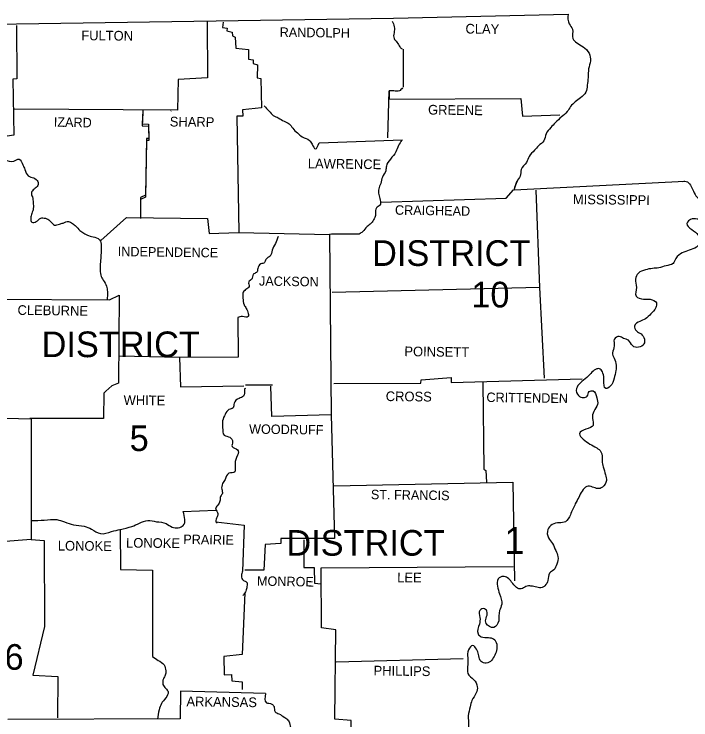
# Model space of a CAD drawing. Extents: x -17742 to 32032, y -17264 to 5867.
# Drawn here: x -16002 to -14349, y -8859 to -7133 of the extents above; entities that cross this region are included whole.
import ezdxf

# ---------------------------------------------------------------- set-up
doc = ezdxf.new("R2010")
doc.units = 0
for name, color, linetype in [('1', 7, 'Continuous'), ('2', 7, 'Continuous'), ('3', 7, 'Continuous')]:
    doc.layers.add(name, color=color, linetype=linetype)

msp = doc.modelspace()

# ---------------------------------------------------------------- linework, layer by layer
at = {"layer": '1'}
for p, q in [((-14779, -7556.5), (-14772.4, -7540.5)), ((-14780.6, -7563.1), (-14774, -7542.7)), ((-15436.7, -8039.7), (-15371.2, -8039.7))]:
    msp.add_line(p, q, dxfattribs=at)
for points in [[(-17667.8, -7158.5), (-16777.9, -7159.1), (-15996.9, -7157.4), (-15075.6, -7143.1), (-14648.6, -7133.2)], [(-15996.9, -7160.7), (-15995.8, -7291.7), (-16005.2, -7292.3), (-16003.5, -7429.3), (-16042.1, -7434.8), (-16038.8, -7471.7), (-16025.5, -7488.8), (-16026.6, -7532.2), (-16101.5, -7535), (-16104.2, -7602.1), (-16172.5, -7604.3), (-16175.8, -7685.8), (-16171.9, -7692.4), (-16170.3, -7822.3), (-16052.5, -7830), (-16054.2, -8120), (-15960.6, -8122.8), (-15960.6, -8417.8), (-16034.4, -8423.3), (-16039.9, -8488.2), (-16163.7, -8488.8)], [(-15530.8, -7152.5), (-15529.7, -7289), (-15601.2, -7292.8), (-15603.4, -7367.7), (-16001.3, -7365.5)], [(-15491.2, -7153), (-15492.8, -7166.3), (-15481.8, -7167.9), (-15482.3, -7174.5), (-15469.7, -7177.3), (-15468.6, -7186.1), (-15462.5, -7189.9), (-15460.9, -7216.3), (-15429.5, -7219.6), (-15429.5, -7243.3), (-15418, -7245), (-15418, -7254.3), (-15408, -7257.1), (-15408.6, -7289), (-15399.8, -7290.6), (-15397.6, -7362.7), (-15444.4, -7367.1), (-15443.8, -7382.5), (-15458.1, -7383.1), (-15453.2, -7667.1), (-15231.4, -7672), (-15227.5, -8113.4), (-15372.3, -8117.3), (-15375, -8043)], [(-15051.4, -7219.1), (-15051.4, -7312.1)], [(-15088.8, -7435.9), (-15086.1, -7320.9), (-15086.1, -7341.3), (-14764.1, -7339.6), (-14759.7, -7382.5), (-14668.9, -7379.2)], [(-15688.2, -7369.3), (-15689.3, -7401.3), (-15673.9, -7402.4), (-15673.3, -7437.6), (-15678.8, -7437.6), (-15681, -7576.3), (-15693.7, -7581.8), (-15693.7, -7628)], [(-15688.2, -7374.3), (-15689.3, -7406.2), (-15673.9, -7407.3), (-15673.3, -7442.5), (-15678.8, -7442.5), (-15681, -7581.2), (-15693.7, -7586.7), (-15693.7, -7633)], [(-15619.4, -7370.4), (-15618.8, -7369.9)], [(-15257.3, -7448), (-15053.1, -7440.9)], [(-14780.6, -7563.1), (-14362.9, -7541.6)], [(-15105.4, -7593.3), (-14799.9, -7583.4), (-14781.7, -7562.5)], [(-14727.8, -7563.6), (-14718.5, -7801.9), (-14707.4, -8023.7)], [(-15790.5, -7686.9), (-15727.8, -7630.2), (-15529.7, -7633), (-15525.8, -7669.8), (-15453.7, -7667.1)], [(-15159.3, -7670.9), (-15226.4, -7670.9), (-15231.4, -7672)], [(-14718.5, -7801.9), (-15225.3, -7813.5)], [(-16052.5, -7830), (-15769.6, -7831.6), (-15745.4, -7820.1), (-15747.1, -8035.3), (-15763.6, -8042.4), (-15778.4, -8055.1), (-15783.4, -8060), (-15783.9, -8121.7), (-15963.9, -8121.7)], [(-15455.9, -7875.1), (-15454.8, -7972), (-15597.9, -7972.5), (-15744.9, -7969.8)], [(-15597.9, -7972.5), (-15595.7, -8044.6), (-15441.1, -8041.9)], [(-15220.9, -8036.4), (-15008.5, -8035.3), (-15007.9, -8027.6), (-14934.2, -8022.1), (-14934.2, -8033.6), (-14613.9, -8024.8)], [(-14857.1, -8033.6), (-14854.4, -8245.5), (-14849.4, -8248.8), (-14847.8, -8277.4)], [(-15436.7, -8049), (-15439.4, -8049.6)], [(-15227.5, -8113.4), (-15219.3, -8415), (-15350.3, -8415.6), (-15350.8, -8427.7), (-15388.8, -8429.9), (-15392.1, -8492.6), (-15438.3, -8492.6)], [(-15220.9, -8286.8), (-14783.9, -8278)], [(-14783.9, -8278), (-14779.5, -8519)], [(-15589.1, -8349.5), (-15509.3, -8345.7)], [(-15509.3, -8374.3), (-15440.5, -8383.1), (-15444.4, -8495.4)], [(-15743.2, -8392.4), (-15742.1, -8491), (-15664.5, -8492.6), (-15664, -8703.9)], [(-15960.6, -8417.8), (-15928.7, -8420), (-15928.1, -8630.2), (-15956.8, -8749.6), (-15895.7, -8752.4), (-15896.2, -8853.6)], [(-15294.1, -8418.3), (-15294.7, -8486.6), (-15269.4, -8486.6), (-15268.3, -8524.5), (-15252.3, -8526.2)], [(-15220.9, -8974.7), (-15178, -8972), (-15178.6, -8860.2), (-15218.7, -8857.5), (-15216.5, -8639), (-15251.2, -8634), (-15252.3, -8487.1), (-14782.8, -8483.8)], [(-15438.3, -8548.2), (-15444.9, -8699), (-15490.1, -8703.9), (-15489, -8748.5), (-15470.8, -8748), (-15470.2, -8763.4), (-15445.5, -8766.1), (-15444.9, -8784.3)], [(-15215.4, -8716.6), (-14905, -8708.9)], [(-15387.7, -8794.2), (-15595.7, -8788.7), (-15596.8, -8856.4), (-16017.8, -8858)]]:
    msp.add_lwpolyline(points, dxfattribs=at)
for points in [[(-14648.6, -7133.2), (-14645.8, -7157.4), (-14638.1, -7170.1), (-14637, -7193.2), (-14627.6, -7203.1), (-14611.7, -7213), (-14597.4, -7229), (-14594.1, -7247.7), (-14598.5, -7267), (-14599.6, -7288.4), (-14601.8, -7307.1), (-14605.1, -7324.2), (-14618.3, -7338), (-14630.9, -7347.9), (-14642.5, -7359.4), (-14650.8, -7371.5), (-14665.1, -7384.7), (-14679.4, -7398.5), (-14690.9, -7410.6), (-14702.5, -7426), (-14708, -7443.1), (-14720.7, -7455.2), (-14730.6, -7466.2), (-14743.8, -7481.1), (-14750.4, -7495.9), (-14763, -7513), (-14765.8, -7529.5), (-14774, -7542.7), (-14774.6, -7544.9)], [(-15078.4, -7150.3), (-15073.4, -7164.1), (-15074, -7178.9), (-15074, -7192.7), (-15066.8, -7202), (-15059.7, -7213.6), (-15054.2, -7218.5)], [(-15053.6, -7313.7), (-15060.8, -7320.9), (-15074.5, -7320.9), (-15086.1, -7320.9)], [(-15391.5, -7357.8), (-15379.4, -7370.4), (-15369, -7380.9), (-15356.9, -7386.9), (-15342.6, -7395.2), (-15329.9, -7401.8), (-15321.6, -7412.3), (-15310.1, -7423.8), (-15298.5, -7433.2), (-15280.4, -7442), (-15274.3, -7451.3), (-15266.1, -7462.9), (-15257.3, -7448)], [(-15054.7, -7441.4), (-15063, -7454.6), (-15069.6, -7470), (-15082.8, -7487.7), (-15092.7, -7504.7), (-15094.3, -7516.3), (-15102.1, -7531.7), (-15106.5, -7547.1), (-15111.4, -7560.3), (-15111.4, -7574.1), (-15107.6, -7587.8), (-15108.7, -7600.5), (-15116.9, -7606.5), (-15119.1, -7622.5), (-15122.4, -7633.5), (-15129.6, -7644.5), (-15140, -7652.8), (-15151, -7665.4), (-15159.3, -7670.9)], [(-16025.5, -7488.8), (-16003.5, -7492.6), (-15990.3, -7487.7), (-15981, -7502), (-15976, -7513), (-15967.8, -7528.9), (-15954.6, -7533.9), (-15944.6, -7542.7), (-15944.6, -7552.1), (-15953.4, -7560.9), (-15960.1, -7569.7), (-15957.9, -7580.1), (-15955.7, -7594.4), (-15955.7, -7608.2), (-15959, -7620.8), (-15961.7, -7632.4), (-15959, -7642.3), (-15948.5, -7640.7), (-15937.5, -7632.4), (-15925.9, -7632.4), (-15914.9, -7638.5), (-15903.4, -7648.9), (-15891.8, -7646.7), (-15882.5, -7644), (-15869.2, -7640.1), (-15859.9, -7645.1), (-15851.6, -7651.7), (-15841.7, -7662.1), (-15832.4, -7668.7), (-15820.3, -7674.8), (-15805.4, -7678.6), (-15791.6, -7688), (-15789.4, -7703.9), (-15790, -7717.7), (-15791.1, -7734.8), (-15792.2, -7753.5), (-15790.5, -7771.6), (-15784.5, -7783.8), (-15776.8, -7798.1), (-15774.6, -7811.3), (-15775.1, -7832.2)], [(-14369, -7542.1), (-14362.9, -7541.6), (-14344.2, -7561.4), (-14336, -7577.9), (-14323.9, -7587.3), (-14310.1, -7592.2), (-14299.6, -7604.9), (-14292.5, -7618.6), (-14296.3, -7630.8), (-14311.7, -7631.9), (-14328.8, -7634.6), (-14345.3, -7634.1), (-14358.5, -7645.1), (-14346.4, -7659.9), (-14330.5, -7673.7), (-14326.1, -7688.5), (-14334.9, -7702.8), (-14352.5, -7710.6), (-14369.5, -7717.2), (-14384.9, -7730.4), (-14392.1, -7743), (-14409.2, -7748.5), (-14426.8, -7753.5), (-14442.2, -7755.1), (-14459.8, -7758.4), (-14476.9, -7766.7), (-14484, -7781), (-14481.8, -7801.4), (-14482.4, -7822.8), (-14464.2, -7830), (-14448.2, -7830.5), (-14432.8, -7838.8), (-14434.5, -7850.9), (-14446, -7866.3), (-14459.8, -7878.4), (-14473.5, -7884.5), (-14486.2, -7896), (-14481.8, -7907.6), (-14470.2, -7915.3), (-14462, -7927.9), (-14463.1, -7939.5), (-14476.3, -7947.8), (-14490.6, -7944.5), (-14501.1, -7930.7), (-14513.2, -7926.3), (-14523.6, -7921.3), (-14535.7, -7928.5), (-14535.7, -7944.5), (-14540.1, -7961.5), (-14536.3, -7974.2), (-14531.3, -7991.8), (-14531.9, -8005), (-14536.3, -8023.7), (-14545.6, -8043), (-14556.7, -8049), (-14561.1, -8028.1), (-14563.3, -8011), (-14569.9, -8001.1), (-14578.7, -8000.6), (-14590.2, -8008.8), (-14602.9, -8021.5), (-14618.8, -8035.3), (-14628.2, -8049), (-14623.2, -8066.1), (-14611.1, -8070.5), (-14601.8, -8067.2), (-14596.8, -8056.2), (-14587.5, -8054.5), (-14578.7, -8071.6)], [(-15357.4, -7677), (-15364, -7694), (-15371.7, -7710.6), (-15376.7, -7724.9), (-15387.1, -7733.1), (-15390.4, -7740.8), (-15399.8, -7744.1), (-15406.9, -7755.1), (-15410.3, -7765), (-15418, -7769.4), (-15421.8, -7781.5), (-15429, -7788.2), (-15428.4, -7799.2), (-15436.7, -7806.9), (-15443.3, -7815.7), (-15443.3, -7827.8), (-15440.5, -7843.7), (-15435, -7853.1), (-15430.1, -7865.2), (-15430.6, -7872.9), (-15444.4, -7872.9), (-15455.9, -7875.1)], [(-15439.4, -8049.6), (-15442.2, -8067.7), (-15452.6, -8072.7), (-15464.7, -8084.8), (-15467.5, -8095.8), (-15477.4, -8100.2), (-15486.7, -8111.8), (-15492.8, -8127.7), (-15492.8, -8144.2), (-15489, -8162.9), (-15475.2, -8167.9), (-15468.6, -8178.9), (-15469.7, -8190.5), (-15456.5, -8198.2), (-15454.3, -8204.8), (-15456.5, -8211.9), (-15462.5, -8232.3), (-15462, -8246), (-15463.1, -8252.1), (-15477.9, -8256), (-15486.7, -8270.8), (-15492.8, -8281.3), (-15495, -8295), (-15493.4, -8304.9), (-15497.8, -8312.6), (-15499.4, -8324.2), (-15504.9, -8334.1), (-15509.9, -8343.5), (-15504.4, -8354.5), (-15506, -8362.2), (-15509.3, -8374.3), (-15506.6, -8378.1)], [(-14578.7, -8071.6), (-14576.5, -8087.5), (-14585.8, -8104.6), (-14589.1, -8121.7), (-14587.5, -8138.7), (-14605.1, -8148.1), (-14620.5, -8159.1), (-14611.7, -8172.3), (-14595.2, -8184.4), (-14578.7, -8193.8), (-14568.2, -8203.1), (-14565.5, -8225.7), (-14562.7, -8240), (-14557.2, -8259.8), (-14555, -8273.6), (-14564.9, -8290.1), (-14576.5, -8293.4), (-14588.6, -8289.5), (-14602.9, -8288.4), (-14614.4, -8299.4), (-14622.7, -8314.8), (-14630.9, -8330.3), (-14637, -8343.5), (-14643.1, -8357.8), (-14655.2, -8374.3), (-14670, -8377), (-14687.6, -8381.4), (-14698.1, -8393.5), (-14696.4, -8413.9), (-14686.5, -8427.7), (-14678.8, -8444.7), (-14673.3, -8459.6), (-14676.1, -8478.3), (-14683.8, -8492.1), (-14693.7, -8500.3), (-14698.1, -8517.9), (-14705.2, -8531.1), (-14711.9, -8535.5), (-14725.1, -8534.4), (-14739.4, -8531.7), (-14751.5, -8532.8), (-14763, -8538.8), (-14774.6, -8535), (-14786.7, -8521.8), (-14796.6, -8511.9), (-14807.6, -8508), (-14819.2, -8514.1), (-14821.4, -8532.2), (-14815.9, -8550.9), (-14810.9, -8576.3), (-14815.9, -8591.7), (-14817.5, -8617)], [(-15959.5, -8371.5), (-15928.7, -8370.4), (-15898.4, -8369.3), (-15879.2, -8374.8), (-15857.1, -8382), (-15831.3, -8385.3), (-15813.1, -8392.4), (-15791.6, -8403.4), (-15764.1, -8398.5), (-15742.7, -8393), (-15714.6, -8385.8), (-15696.4, -8378.1), (-15675.5, -8371.5), (-15654.6, -8374.3), (-15630.9, -8378.7), (-15616.1, -8387.5), (-15589.1, -8383.6), (-15589.1, -8349.5)], [(-15444.4, -8495.4), (-15446.6, -8506.4), (-15442.2, -8517.9), (-15434.5, -8521.8), (-15433.4, -8532.8), (-15436.1, -8543.8), (-15438.3, -8548.2), (-15443.3, -8554.8)], [(-14817.5, -8617), (-14830.2, -8632.9), (-14848.9, -8623), (-14848.9, -8609.8), (-14846.1, -8596.1), (-14852.7, -8587.3), (-14864.3, -8591.1), (-14864.3, -8608.2), (-14865.4, -8624.7), (-14868.7, -8648.4), (-14861, -8655.5), (-14843.4, -8657.7), (-14830.7, -8661), (-14823, -8673.7), (-14823.6, -8689.1), (-14829.6, -8703.9), (-14838.4, -8716), (-14852.2, -8720.5), (-14863.2, -8713.3), (-14867.6, -8699), (-14872.6, -8686.3), (-14881.9, -8677), (-14891.8, -8687.4), (-14894, -8706.7), (-14893.5, -8723.2), (-14893.5, -8745.8), (-14879.2, -8760.6), (-14870.4, -8777.7), (-14873.1, -8793.1), (-14883.6, -8811.3), (-14888, -8827.2), (-14892.4, -8848.7), (-14891.8, -8872.3), (-14895.7, -8895.5), (-14903.4, -8910.9), (-14917.7, -8923.5), (-14927, -8931.8), (-14934.7, -8940), (-14938.6, -8956.6), (-14941.3, -8968.1), (-14951.8, -8981.9), (-14960.1, -8983), (-14966.7, -8977.5), (-14968.9, -8968.1), (-14968.9, -8958.8), (-14973.3, -8949.4), (-14987, -8945.5), (-14998, -8946.1), (-15003, -8953.8), (-14995.8, -8975.3), (-14993.1, -8989), (-14996.9, -9007.7), (-14994.7, -9009.9), (-15014.5, -9020.4), (-15030.5, -9022), (-15043.7, -9025.9), (-15056.4, -9034.2), (-15062.4, -9046.3), (-15071.2, -9056.2), (-15078.9, -9065.5), (-15089.4, -9069.9), (-15101, -9067.7), (-15116.4, -9066.1), (-15125.2, -9077.1), (-15122.4, -9093), (-15112, -9102.4), (-15096.5, -9106.8), (-15080.6, -9105.7), (-15065.2, -9104), (-15050.9, -9111.8), (-15053.6, -9126.6), (-15067.4, -9133.8), (-15087.7, -9136), (-15104.3, -9134.3), (-15124.1, -9138.7), (-15134, -9151.4), (-15128.5, -9170.6), (-15107, -9178.3), (-15097.1, -9196.5), (-15096.5, -9213.6), (-15103.7, -9236.1), (-15113.6, -9246.6), (-15132.9, -9251), (-15147.7, -9253.7), (-15149.9, -9279.1), (-15156.5, -9291.7), (-15168.1, -9295.6), (-15184.6, -9287.3), (-15194.5, -9283.5), (-15206.6, -9278), (-15222, -9268.6), (-15233.6, -9270.3), (-15230.3, -9294.5), (-15229.2, -9295.6), (-15216, -9313.7), (-15202.8, -9328), (-15196.7, -9345.1)], [(-15664, -8703.9), (-15650.2, -8713.3), (-15635.9, -8724.3), (-15632, -8739.2), (-15633.1, -8749.6), (-15637.5, -8758.4), (-15638.6, -8772.2), (-15632, -8782.1), (-15626, -8790.3), (-15632, -8805.2), (-15642.5, -8819), (-15648, -8834.4), (-15651.9, -8857.5)], [(-15387.7, -8794.2), (-15386, -8816.8), (-15372.8, -8820.1), (-15367.3, -8826.1), (-15364.6, -8838.8), (-15355.2, -8844.3), (-15342.6, -8852), (-15334.9, -8857.5), (-15329.3, -8866.3), (-15326, -8880.6), (-15317.2, -8890), (-15305.1, -8894.4), (-15296.3, -8904.8), (-15290.8, -8919.7), (-15282, -8926.3), (-15273.2, -8937.8), (-15268.8, -8942.8), (-15261.1, -8956), (-15253.4, -8962.6), (-15247.9, -8966.5), (-15239.1, -8969.2), (-15228.1, -8976.4), (-15220.9, -8987.4), (-15220.9, -8995.6), (-15223.7, -9008.3), (-15225.9, -9021.5), (-15227, -9036.4), (-15228.1, -9049.6), (-15223.1, -9060.6), (-15225.9, -9077.1), (-15231.4, -9085.9), (-15231.9, -9098), (-15233.6, -9116.2), (-15235.8, -9126.6), (-15240.7, -9143.7), (-15247.9, -9152.5)]]:
    msp.add_spline(points, degree=3, dxfattribs=at)

# ---------------------------------------------------------------- texts
msp.add_text('1', height=66, dxfattribs=at).set_placement((-14804.3, -8453.5))
at = {"layer": '2'}
for s, height, rotation, p in [('CLAY', 23.66, 359.2258, (-14899.5, -7180.6)), ('FULTON', 23.66, 359.4996, (-15838.4, -7197.1)), ('RANDOLPH', 23.11, 359.2583, (-15353.6, -7188.8)), ('GREENE', 23.67, 359.2361, (-14990.9, -7378.7)), ('IZARD', 23.11, 358.9258, (-15905.6, -7408.4)), ('SHARP', 23.66, 359.3905, (-15622.1, -7407.9)), ('LAWRENCE', 23.67, 359.2678, (-15284.8, -7510.2)), ('MISSISSIPPI', 23.66, 359.3097, (-14637, -7597.7)), ('CRAIGHEAD', 23.11, 359.1159, (-15071.8, -7623.6)), ('INDEPENDENCE', 23.108, 359.2187, (-15749.3, -7724.9)), ('JACKSON', 23.11, 359.1352, (-15404.2, -7797)), ('CLEBURNE', 23.66, 359.2535, (-15994.2, -7868.5)), ('POINSETT', 23.66, 359.1987, (-15048.8, -7969.5)), ('CROSS', 23.66, 359.3839, (-15094.3, -8079.3)), ('CRITTENDEN', 23.11, 359.213, (-14848.3, -8081.5)), ('WHITE', 23.67, 359.3139, (-15735, -8088.6)), ('WOODRUFF', 23.11, 359.2748, (-15428.4, -8159.1)), ('ST. FRANCIS', 23.108, 359.2216, (-15130.7, -8319.2)), ('LONOKE', 23.67, 359.4974, (-15895.7, -8444.7)), ('LONOKE', 23.67, 359.4974, (-15728.9, -8437.6)), ('PRAIRIE', 23.11, 359.2116, (-15589.1, -8428.8)), ('LEE', 23.67, 359.4327, (-15066.3, -8522.3)), ('MONROE', 23.11, 359.0331, (-15409.1, -8530.6)), ('PHILLIPS', 23.66, 359.3179, (-15124.1, -8750.2)), ('ARKANSAS', 23.66, 359.2678, (-15581.4, -8825.6))]:
    msp.add_text(s, height=height, rotation=rotation, dxfattribs=at).set_placement(p)
at = {"layer": '3'}
for s, height, p in [('DISTRICT', 62.74, (-15127.6, -7748.9)), ('10', 62.74, (-14885.1, -7850.4)), ('DISTRICT', 62.74, (-15935.3, -7972)), ('5', 62.7, (-15720.1, -8201.5)), ('DISTRICT', 62.74, (-15337.1, -8457.4)), ('DISTRICT 6', 62.74, (-16436.1, -8736.4))]:
    msp.add_text(s, height=height, dxfattribs=at).set_placement(p)

doc.saveas('drawing.dxf')
